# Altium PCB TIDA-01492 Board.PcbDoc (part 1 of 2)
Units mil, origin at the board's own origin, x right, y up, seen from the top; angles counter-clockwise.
Board outline 4930.03 x 2625.03 mil, 4 copper layers (Top Layer, Signal Layer 1, Signal Layer 2, Bottom Layer), stack 38.4 mil thick; 141 components, 49 nets, 383 pads, 426 vias.
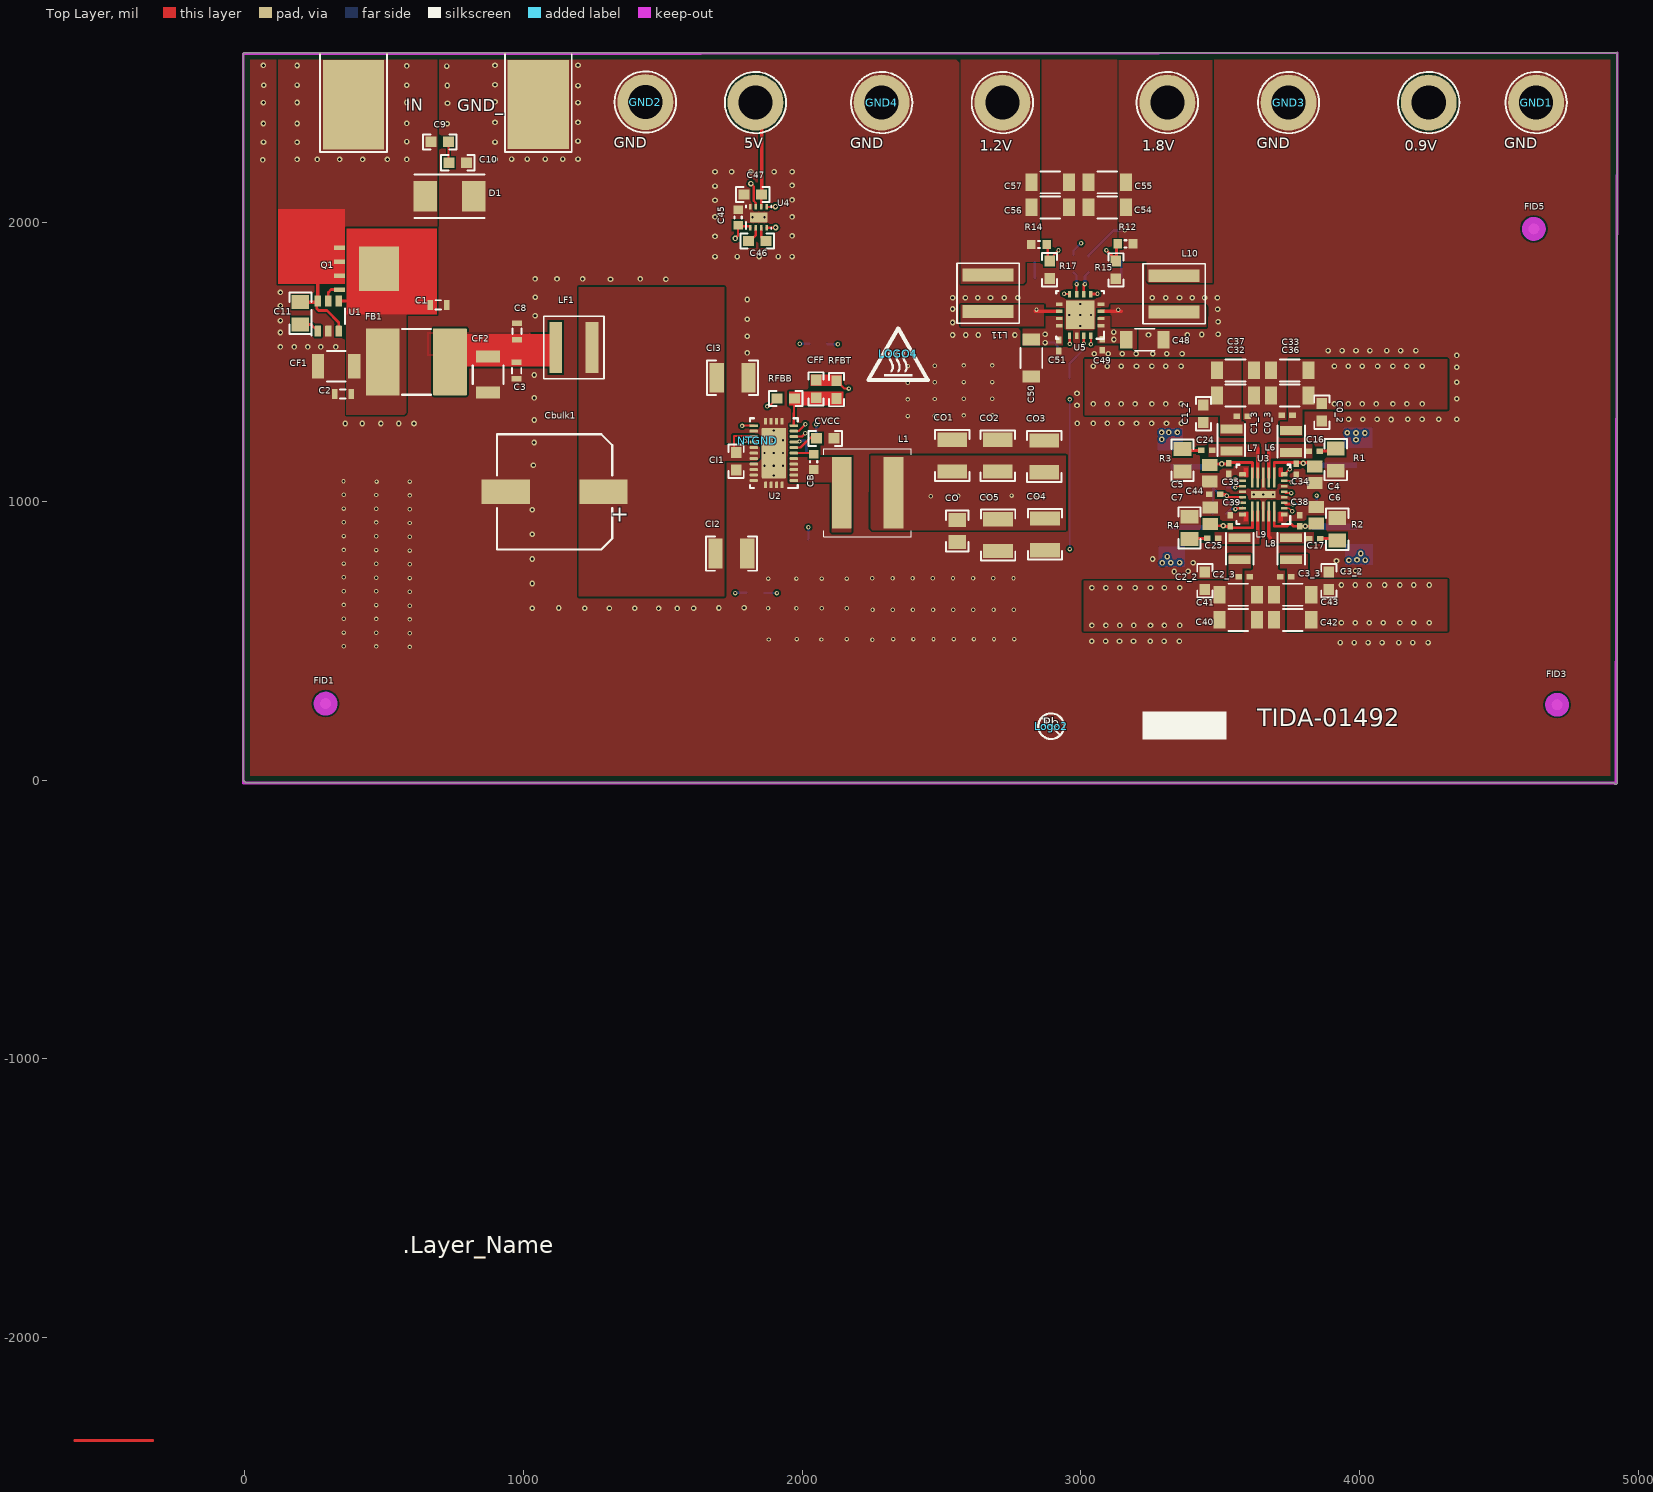
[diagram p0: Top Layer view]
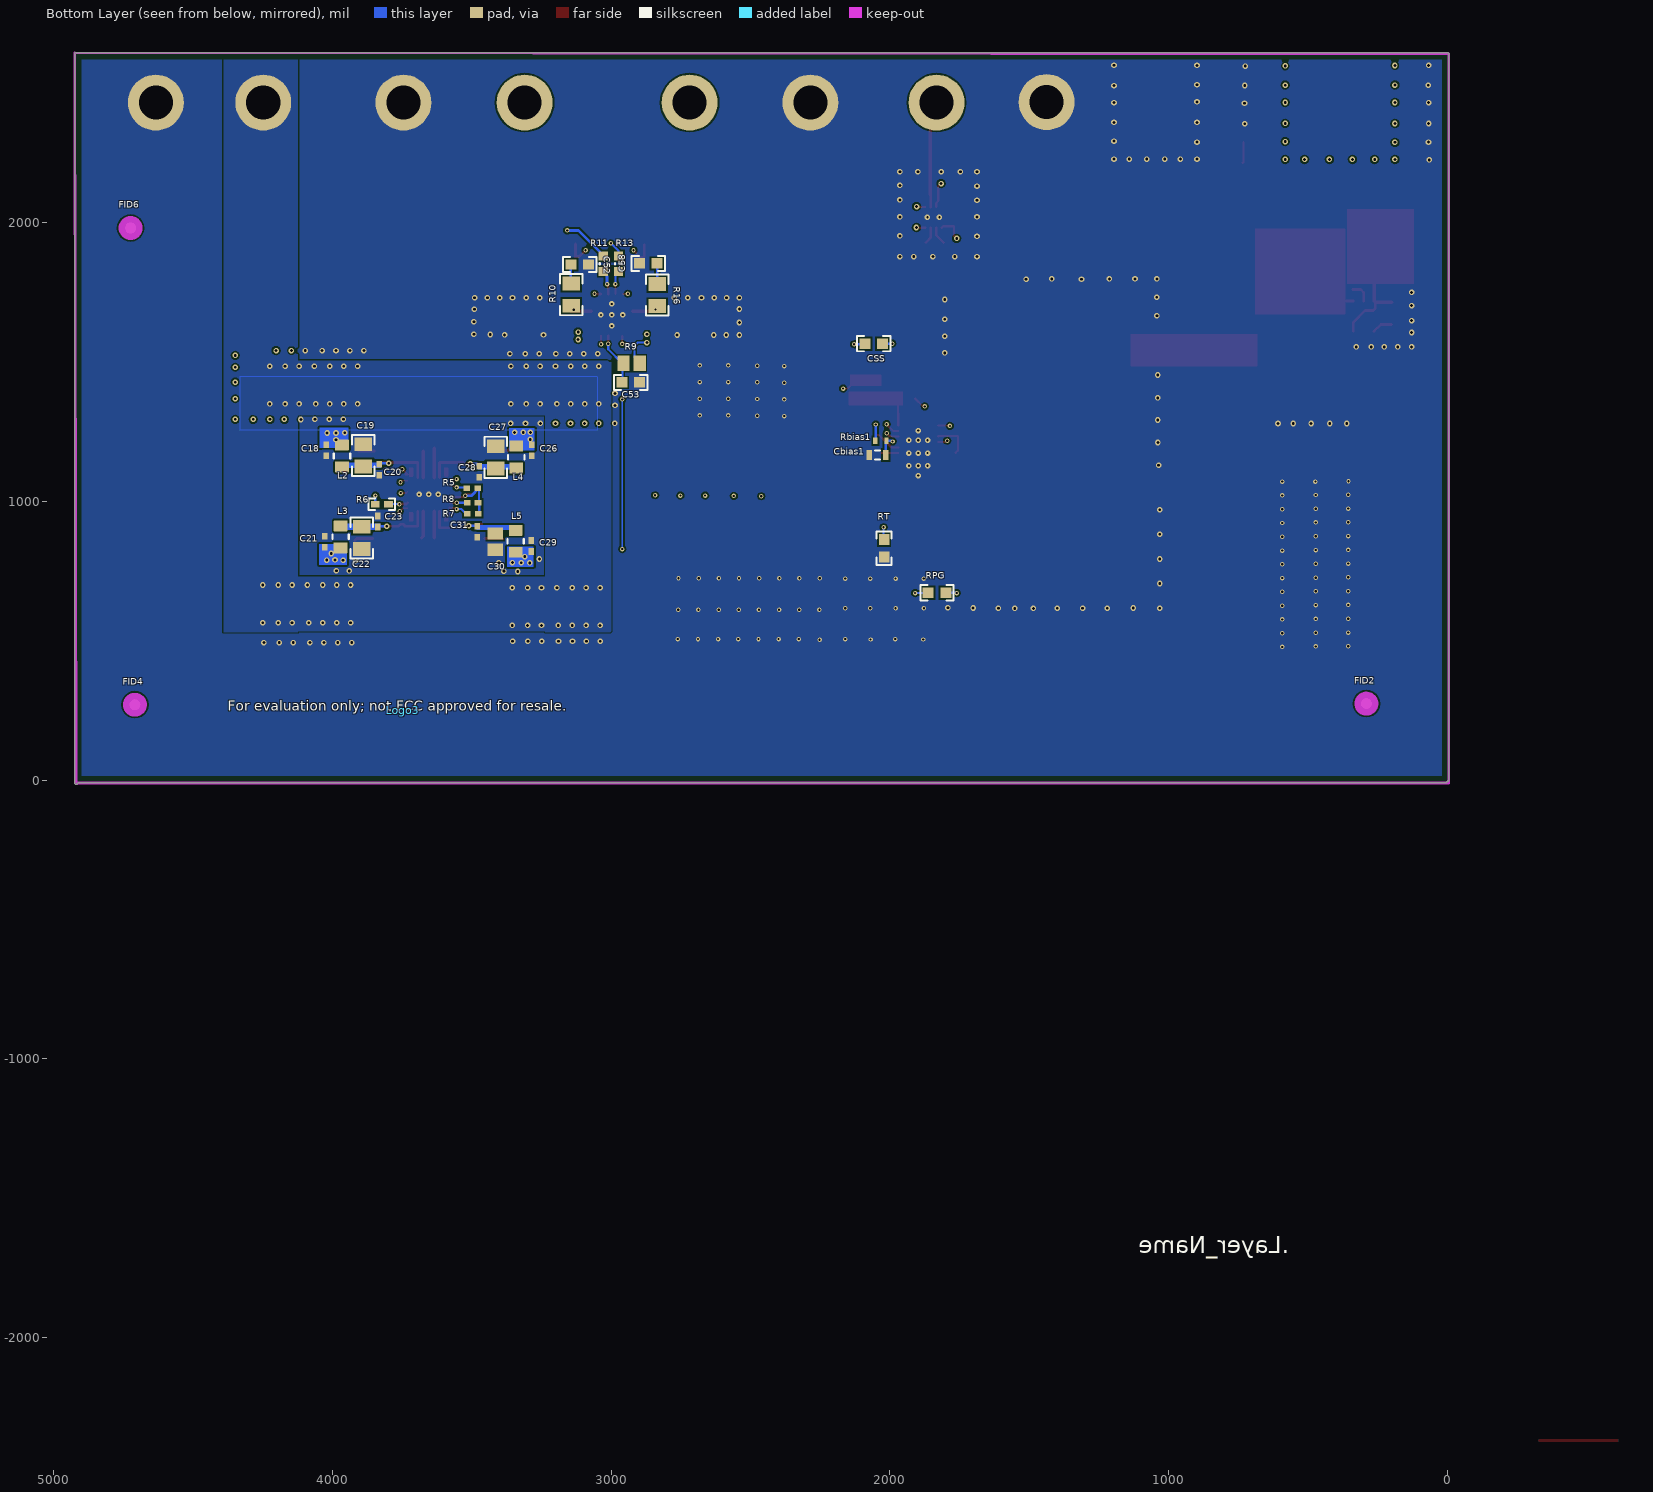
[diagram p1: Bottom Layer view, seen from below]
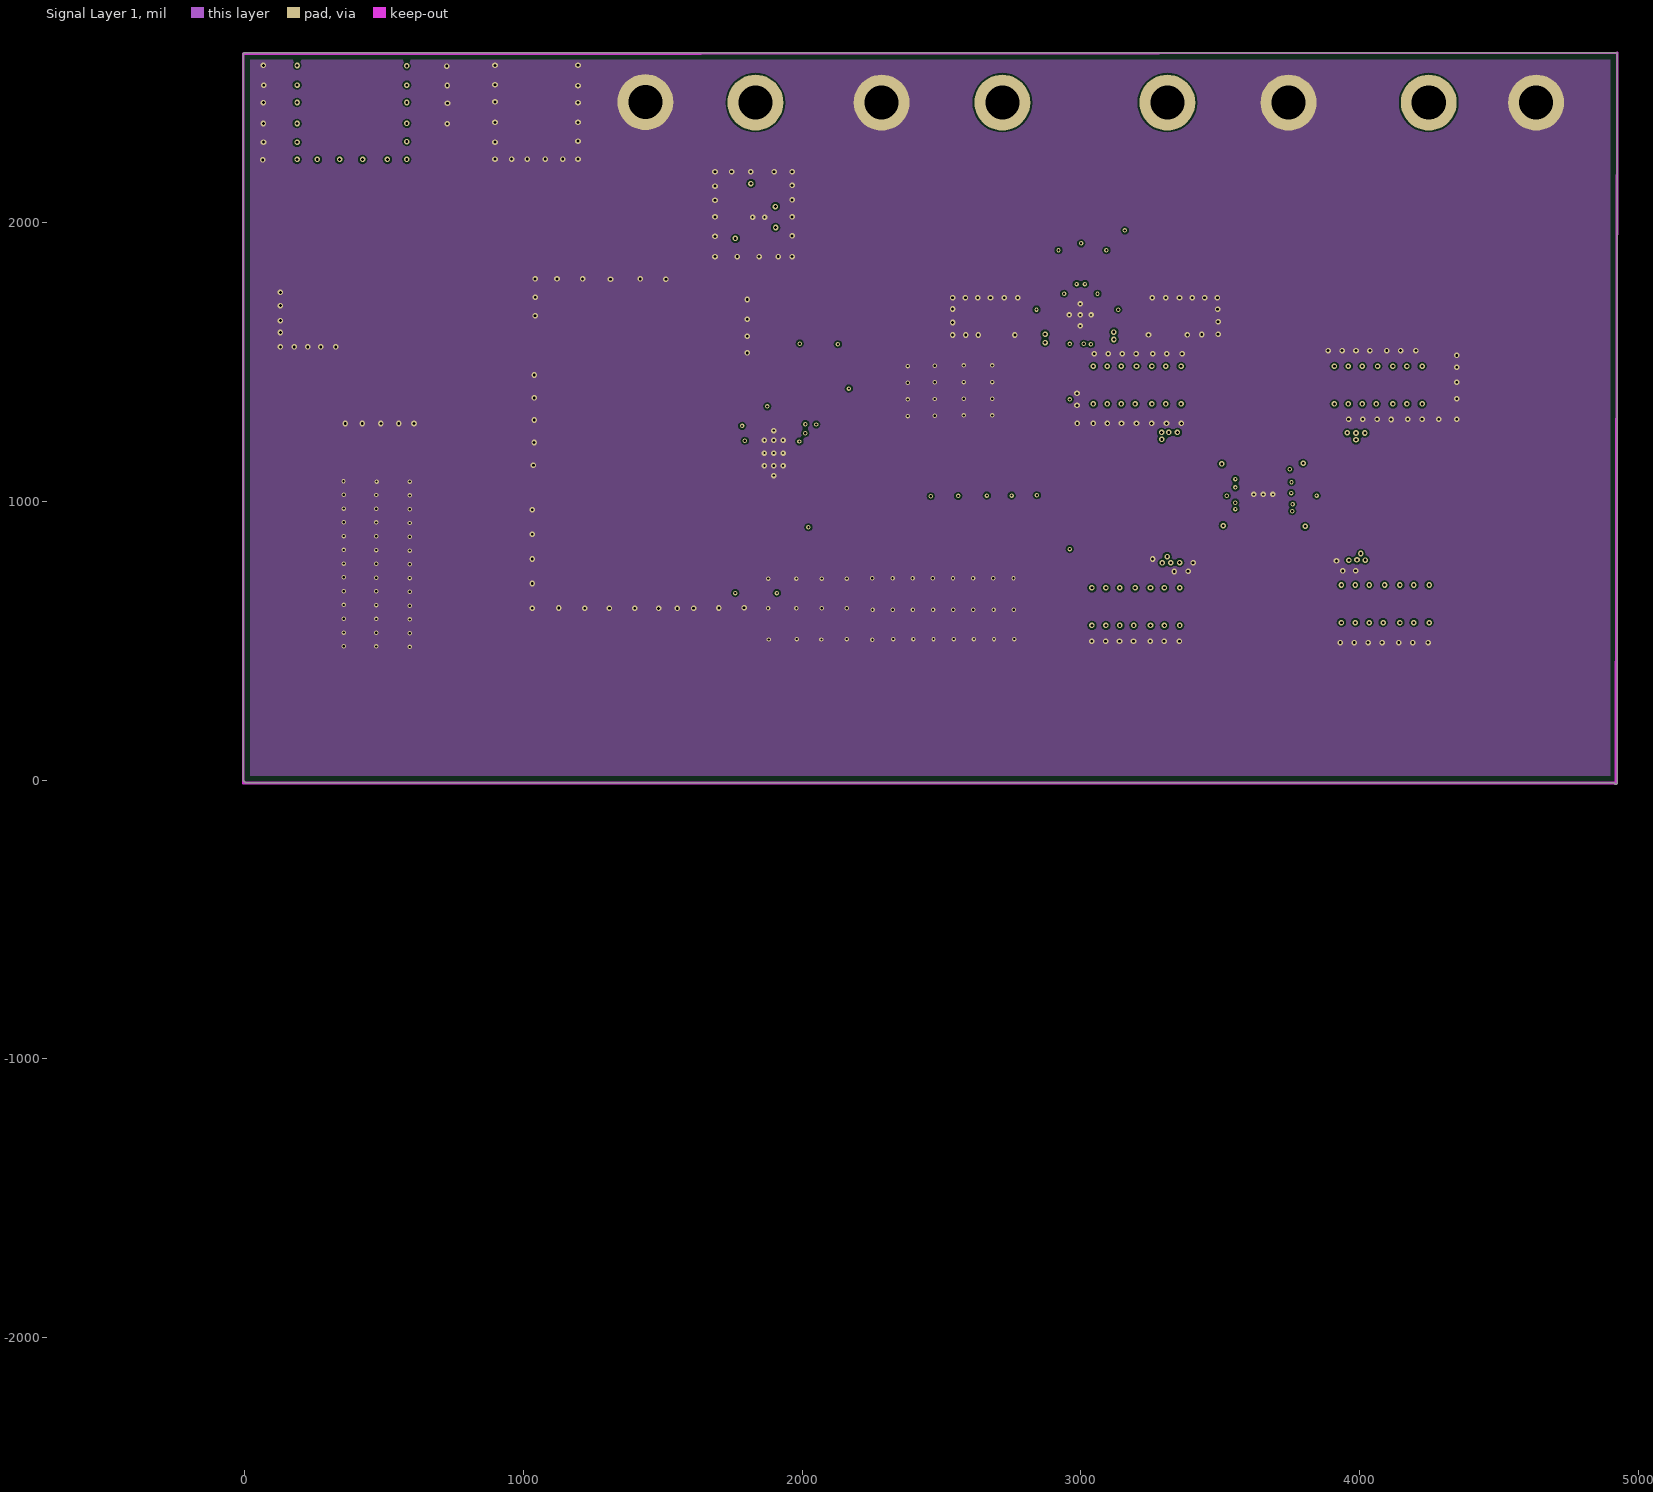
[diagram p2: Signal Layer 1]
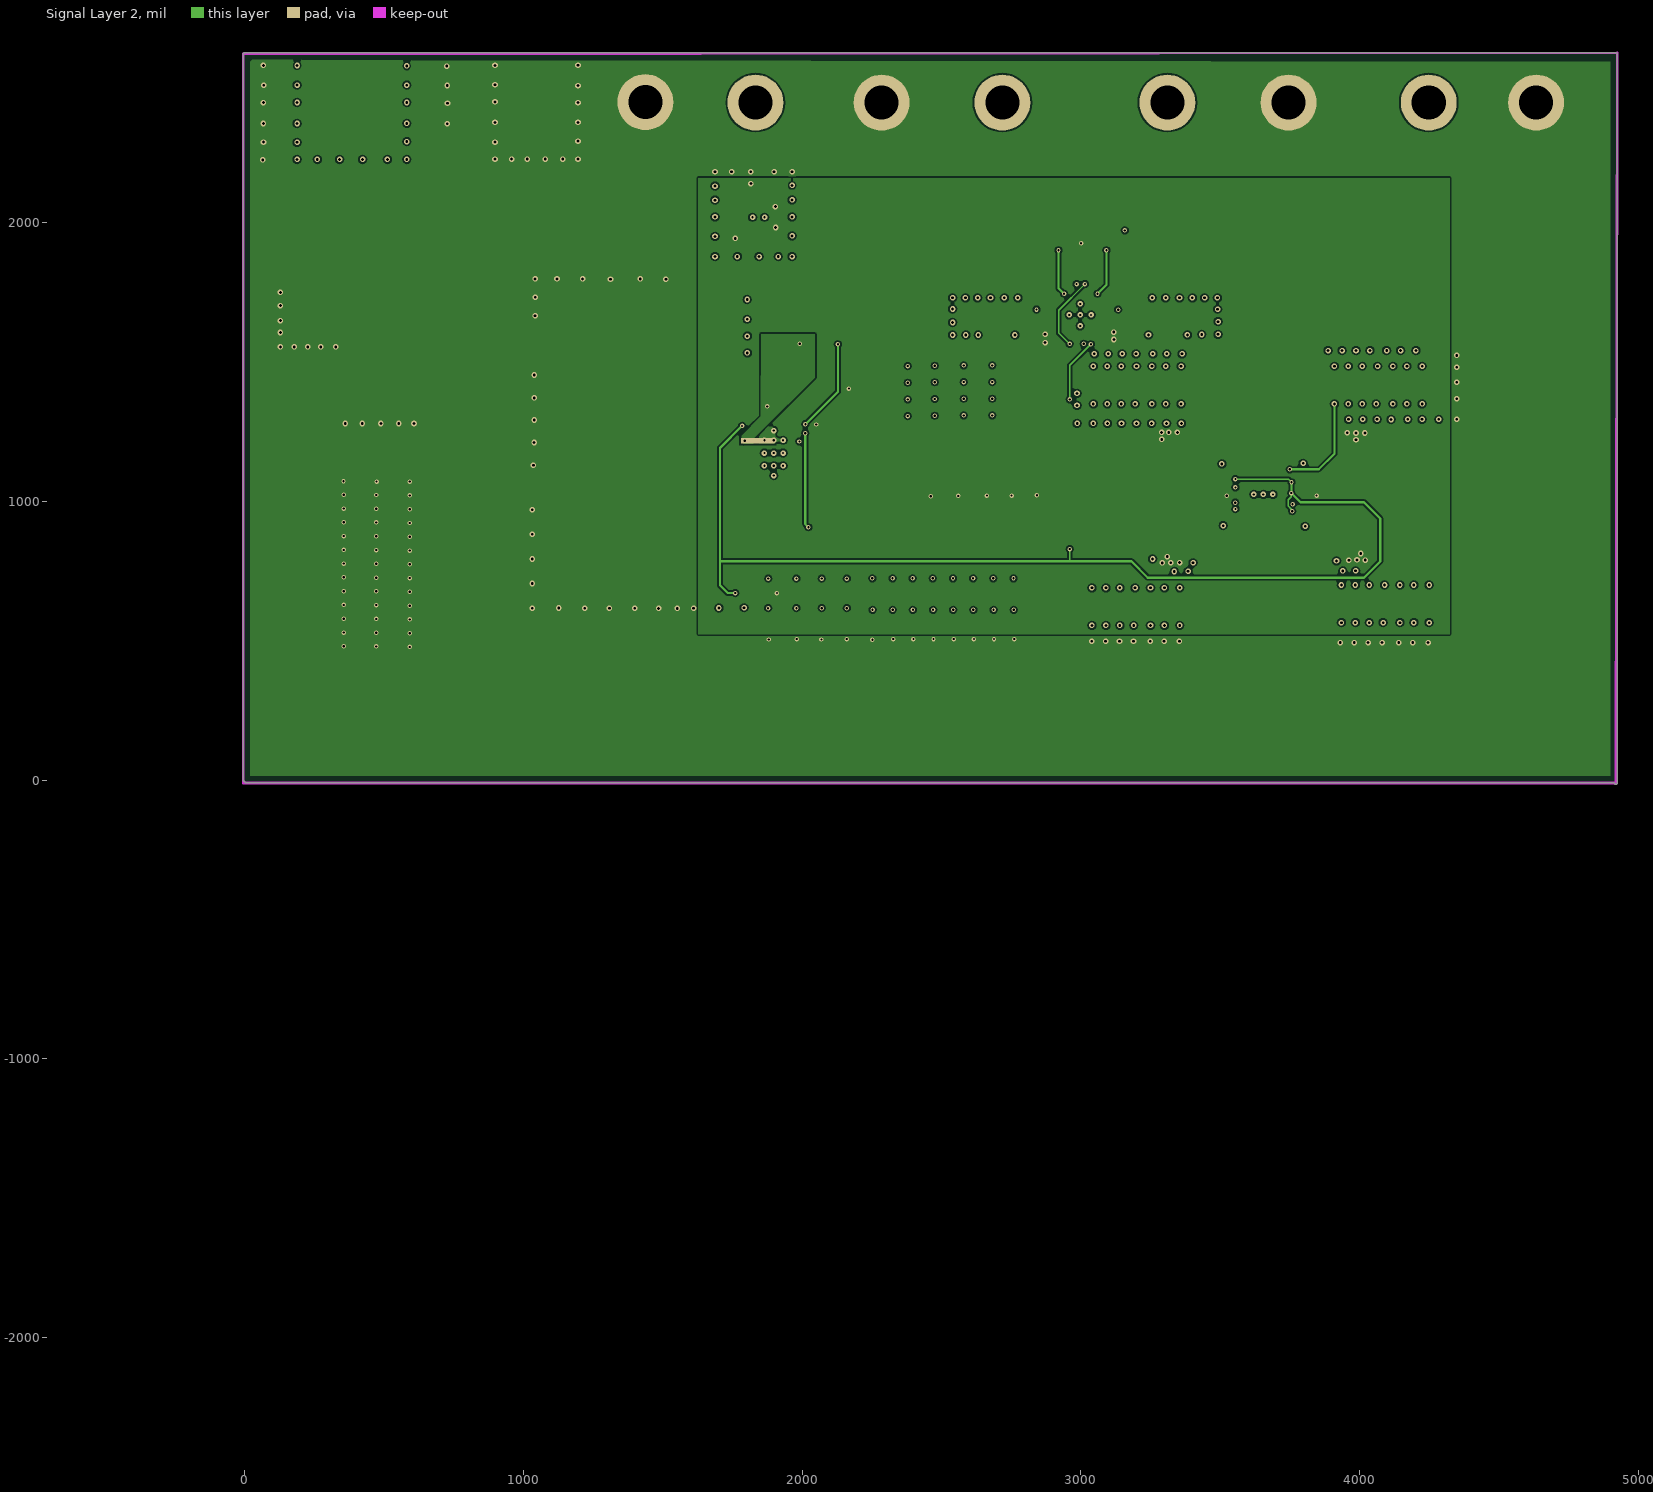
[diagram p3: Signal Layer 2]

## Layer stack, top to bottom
Top Solder: solder mask 0.4, Solder Resist, Dk 3.5
Top Layer: signal copper 2.8
Dielectric 2: core 10, FR-4, Dk 4.2
Signal Layer 1: signal copper 1.4
Dielectric 3: core 10, FR-4, Dk 4.2
Signal Layer 2: signal copper 1.4
Dielectric1: core 10, FR-4, Dk 4.2
Bottom Layer: signal copper 2.8
Bottom Solder: solder mask 0.4, Solder Resist, Dk 3.5

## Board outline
-0.01,-5.01 cw(c0,0) -5.01,0 -5.01,2605 cw(c0,2605) 0,2610.02 4920,2610.02 cw(c4920,2605) 4925.02,2605 4925.02,-10 cw(c4920,-10) 4914.98,-10.01 5,-10.01 cw(c5,-5)

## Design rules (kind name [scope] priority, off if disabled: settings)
AcuteAngle [All] p1: minimum=4.50000000000000E+0001 checktracksonly=FALSE
AssemblyTestPointUsage [All] p1: valid=2
BoardOutlineClearance BoardOutlineClearance_MountingHoles [OnCopper and InComponentClass('Mounting Holes')] p1: gap=40 ignorepadtopadclearanceinfootprint=FALSE
BoardOutlineClearance BoardOutlineClearance_Poly [OnCopper and IsPoly] p2: gap=25 ignorepadtopadclearanceinfootprint=FALSE
BoardOutlineClearance [OnCopper and Not InComponentClass('Logo') and not InComponentClass('FiducialMark') and not InRegion(1000,500,4000,800) and not InPoly] p3: gap=25 ignorepadtopadclearanceinfootprint=FALSE
Clearance Clearance_Keepouts [((IsTrack Or IsArc) And Not InPoly) And IsFree and IsKeepOut vs ((IsTrack Or IsArc) And Not InPoly) And IsFree and IsKeepOut] p1: gap=0 ignorepadtopadclearanceinfootprint=FALSE
Clearance Clearance_Poly [InPolygon] p2: gap=6 ignorepadtopadclearanceinfootprint=FALSE except(0: Arc-Hole Track-Hole SMDPad-Hole THPad-Hole Via-Hole Fill-Hole Poly-Hole Region-Hole Text-Hole)
Clearance [All] p3: gap=5 ignorepadtopadclearanceinfootprint=FALSE except(0: Arc-Hole Track-Hole SMDPad-Hole THPad-Hole Via-Hole Fill-Hole Poly-Hole Region-Hole Text-Hole)
ComponentClearance ComponentClearance_MountingHoles_FiducialMarks [InComponentClass('Mounting Holes') vs InComponentClass('FiducialMark')] p1: gap=50 collisioncheckmode=3 verticalgap=10 showdistances=TRUE
ComponentClearance ComponentClearance_Shunt [InComponentClass('Header') vs InComponentClass('Shunt')] p2: gap=0 collisioncheckmode=3 verticalgap=0 showdistances=FALSE
ComponentClearance ComponentClearance_Logo [InComponentClass('Logo')] p3: gap=50 collisioncheckmode=3 verticalgap=10 showdistances=FALSE
ComponentClearance ComponentClearance_ScrewToNut [(HasFootprint('NY PMS 440 0025 PH')) vs (HasFootprint('Keystone_1902C'))] p4: gap=5 collisioncheckmode=3 verticalgap=10 showdistances=FALSE
ComponentClearance ComponentClearance_MountingHoles [InComponentClass('Mounting Holes')] p5: gap=250 collisioncheckmode=3 verticalgap=100000 showdistances=FALSE
ComponentClearance ComponentClearance_SmallPassives [HasFootprint('0201*') or HasFootprint('0402*') or HasFootprint('0508') or HasFootprint('0603*') or HasFootprint('0612') or HasFootprint('0805*') or HasFootprint('0815*') or HasFootprint('0830*') or HasFootprint('1206*') or HasFootprint('1210*') or HasFootprint('1808*') or HasFootprint('1812*') or HasFootprint('1825*') or HasFootprint('2010*') or HasFootprint('2220*') or HasFootprint('2225*') or HasFootprint('2512*') or HasFootprint('2728*') or HasFootprint('3518*') vs HasFootprint('0201*') or HasFootprint('0402*') or HasFootprint('0508') or HasFootprint('0603*') or HasFootprint('0612') or HasFootprint('0805*') or HasFootprint('0815*') or HasFootprint('0830*') or HasFootprint('1206*') or HasFootprint('1210*') or HasFootprint('1808*') or HasFootprint('1812*') or HasFootprint('1825*') or HasFootprint('2010*') or HasFootprint('2220*') or HasFootprint('2225*') or HasFootprint('2512*') or HasFootprint('2728*') or HasFootprint('3518*')] p6: gap=14.96 collisioncheckmode=3 verticalgap=10 showdistances=FALSE
ComponentClearance ComponentClearance_THtoSMT [IsThruComponent vs IsSMTComponent] p7: gap=40 collisioncheckmode=3 verticalgap=30 showdistances=FALSE
ComponentClearance ComponentClearance_THtoTH [IsThruComponent vs IsThruComponent] p8: gap=30 collisioncheckmode=3 verticalgap=30 showdistances=FALSE
ComponentClearance [InComponent('No Component') vs InComponent('No Component')] p9: gap=10 collisioncheckmode=3 verticalgap=10 showdistances=FALSE
DiffPairsRouting [All] p1: maxlimit=100 minlimit=10 mostfreqgap=10 toplayer_minwidth=15 toplayer_maxwidth=15 toplayer_prefwidth=15 midlayer1_minwidth=15 midlayer1_maxwidth=15 midlayer1_prefwidth=15 midlayer2_minwidth=15 midlayer2_maxwidth=15 midlayer2_prefwidth=15 bottomlayer_minwidth=15 bottomlayer_maxwidth=15 bottomlayer_prefwidth=15 maxuncoupledlength=1000
FabricationTestPointUsage TestPointUsage [All] p1: valid=2 allowmultiple=FALSE
FabricationTestpoint Testpoint [All] p1: side=3 testpointundercomponent=TRUE minsize=40 maxsize=100 preferedsize=60 minholesize=0 maxholesize=40 preferedholesize=32 testpointgrid=1 allowsidetop=TRUE allowsidebottom=TRUE usegrid=TRUE gridtolerance=0.01
FanoutControl Fanout_LCC [IsLCC] p1: bgadir=Out bgaviamode=Centered fanoutstyle=Auto fanoutdirection=Alternating viagrid=1 // Fanout_LCC (Default Rule)
FanoutControl Fanout_BGA [IsBGA] p2: bgadir=Out bgaviamode=Centered fanoutstyle=Auto fanoutdirection=Alternating viagrid=1 // Fanout_BGA (Default Rule)
FanoutControl Fanout_Default [All] p4: bgadir=Out bgaviamode=Centered fanoutstyle=Auto fanoutdirection=Alternating viagrid=1 // Fanout_Default (Default Rule)
FanoutControl Fanout_Small [(CompPinCount < 5)] p5: bgadir=Out bgaviamode=Centered fanoutstyle=Auto fanoutdirection=OutThenIn viagrid=1 // Fanout_Small (Default Rule)
HoleSize [All] p1: absolutevalues=TRUE maxlimit=251 minlimit=7.87 maxpercent=80.000 minpercent=20.000
MinimumAnnularRing MinimumAnnularRing_ThermalPadVias [IsVia and InAnyComponent] p1: minimumring=5.91
MinimumAnnularRing [All] p2: minimumring=4
MinimumSolderMaskSliver MinimumSolderMaskSliver_Logo [InComponentClass('Logo') vs InComponentClass('Logo')] p1: minsoldermaskwidth=0.7
MinimumSolderMaskSliver [All] p2: minsoldermaskwidth=3.94
PlaneConnect [All] p1: planeconnectstyle=Relief reliefexpansion=10 reliefentries=4 reliefconductorwidth=10 reliefairgap=10
PolygonConnect [All] p1: connectstyle=Direct reliefconductorwidth=10 reliefentries=4 polygonreliefangle="90 Angle" airgapwidth=10
RoomDefinition TIDA-01492_EVM_Hardware [InComponentClass('TIDA-01492_EVM_Hardware')] p1 off: confinementstyle=ConfineIn formatcopy=TRUE lockcomponents=FALSE outline -702,-2374 1298,-2374 1298,-1374 -702,-1374
RoomDefinition "Memory + IO + CAN Supply" [InComponentClass('Memory + IO + CAN Supply')] p2 off: confinementstyle=ConfineIn formatcopy=TRUE lockcomponents=FALSE outline -702,-2374 1298,-2374 1298,-1374 -702,-1374
RoomDefinition "Main Supply + Smart Diode" [InComponentClass('Main Supply + Smart Diode')] p3 off: confinementstyle=ConfineIn formatcopy=TRUE lockcomponents=FALSE outline -702,-2374 1298,-2374 1298,-1374 -702,-1374
RoomDefinition "Core-Voltage Supply" [InComponentClass('Core-Voltage Supply')] p4 off: confinementstyle=ConfineIn formatcopy=TRUE lockcomponents=FALSE outline -702,-2374 1298,-2374 1298,-1374 -702,-1374
RoutingVias ThermalPadVias [IsVia and InAnyComponent] p1: holewidth=7.87 width=19.68 viastyle="Through Hole" minholewidth=7.87 minwidth=19.68 maxholewidth=12.99 maxwidth=23.62
RoutingVias [All] p2: holewidth=16 width=34 viastyle="Through Hole" minholewidth=8 minwidth=16 maxholewidth=40 maxwidth=65
SilkToBoardRegionClearance [Not ((IsComment or IsDesignator) And (Hide <> 'False')) and not InRegion(1000,500,4000,800)] p1:
SilkToSilkClearance SilkToSilkClearance_Pb-FreeLogo [(HasFootprint('Pb-Free_Overlay_Medium') OR HasFootprint('Pb-Free_Overlay_Small')) vs (HasFootprint('Pb-Free_Overlay_Medium') OR HasFootprint('Pb-Free_Overlay_Small'))] p1: silktosilkclearance=0
SilkToSilkClearance [All] p2: silktosilkclearance=4
SilkToSolderMaskClearance SilkToComponentPadClearance [(IsPad or IsFill or IsRegion) and InAnycomponent] p1: minsilkscreentomaskgap=5 clearancetoexposedcopper=TRUE
SilkToSolderMaskClearance "Silk to Solder Mask Opening" [All] p2: minsilkscreentomaskgap=4 clearancetoexposedcopper=FALSE
SolderMaskExpansion [All] p1: expansion=1.97
Width [All] p1: maxlimit=100 minlimit=6 preferedwidth=10 checkconnectedcopper=TRUE
15 further rules are at their usual default settings.

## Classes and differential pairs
component class TIDA-01492_EVM_Hardware: !PCB1 FID1 FID2 FID3 FID4 FID5 FID6 Logo2 Logo3
component class "Main Supply + Smart Diode": C1 C2 C3 C8 C9 C10 C11 CB Cbias1 Cbulk1 CF1 CF2 CFF CI1 CI2 CI3 CO CO1 CO2 CO3 CO4 CO5 CSS CVCC D1 FB1 GND_ IN L1 LF1 LOGO4 NTGND Q1 R_FB1 Rbias1 RFBB RFBT RPG RT U1 U2
component class "Core-Voltage Supply": 0.9V C0_2 C0_3 C1_1 C1_2 C1_3 C2_2 C2_3 C3_2 C3_3 C4 C5 C6 C7 C16 C17 C18 C19 C20 C21 C22 C23 C24 C25 C26 C27 C28 C29 C30 C31 C32 C33 C34 C35 C36 C37 C38 C39 C40 C41 C42 C43 C44 GND1 L2 L3 L4 L5 L6 L7 L8 L9 R1 R2 R3 R4 R5 R6 R7 R8 U3
component class "Memory + IO + CAN Supply": 1.2V 1.8V 5V C45 C46 C47 C48 C49 C50 C51 C52 C53 C54 C55 C56 C57 C58 C59 C60 GND2 GND3 GND4 L10 L11 R9 R10 R11 R12 R13 R14 R15 R16 R17 U4 U5

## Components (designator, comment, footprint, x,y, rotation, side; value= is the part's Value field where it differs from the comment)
0.9V "0.9V" Keystone1503-2 4248.5,2431 r0 top value=Double
1.2V "1.2V" Keystone1503-2 2718.5,2431 r0 top value=Double
1.8V "2010-10-20" Keystone1503-2 3310.5,2431 r0 top value=Double
5V "5V" Keystone1503-2 1832.5,2431 r0 top value=Double
C0_2 "GRM188R71C104KA01D" 0603 3865,1320 r90 top value=0.1uF
C0_3 "GRM155R71H332KA01D" 0402L 3740,1310 r180 top value=3300pF
C1 "GCM188R71C104KA37J" 0603S 695,1705 r0 top value=0.1uF
C1_2 "GRM188R71C104KA01D" 0603 3440,1315 r90 top value=0.1uF
C1_3 "GRM155R71H332KA01D" 0402L 3580,1305 r0 top value=3300pF
C2 "GCM188R71C104KA37J" 0603S 352.5,1385.5 r180 top value=0.1uF
C2_2 "GRM188R71C104KA01D" 0603 3445,715 r270 top value=0.1uF
C2_3 "GRM155R71H332KA01D" 0402L 3586,729.5 r0 top value=3300pF
C3 "GCM188R71C104KA37J" 0603S 975.5,1469.5 r270 top value=0.1uF
C3_2 "GRM188R71C104KA01D" 0603 3890,715 r270 top value=0.1uF
C3_3 "GRM155R71H332KA01D" 0402L 3735,730 r180 top value=3300pF
C4 "GCM21BR71A106KE22L" 0805L 3840,1095 r270 top value=10uF
C5 "GCM21BR71A106KE22L" 0805L 3463,1101 r90 top value=10uF
C6 "GCM21BR71A106KE22L" 0805L 3845,950 r90 top value=10uF
C7 "GCM21BR71A106KE22L" 0805L 3465,949 r270 top value=10uF
C8 "GCM188R71C104KA37J" 0603S 977,1610 r90 top value=0.1uF
C9 "C0603C472J1GAC7867" 0603 700,2290 r0 top value=4700pF
C10 "C0603C472J1GAC7867" 0603 765,2215 r180 top value=4700pF
C11 "C2012X5R1H225K125AB" 0805_HV 200,1675 r270 top value=2.2uF
C16 "GRM155R71H391KA01D" 0402L 3837,1180.5 r0 top value=390pF
C17 "GRM155R71H391KA01D" 0402L 3840,866.5 r0 top value=390pF
C18 "GRM155R71H682KA88D" 0402L 4022,1183 r270 bottom value=6800pF
C19 "GRM21BR60J106KE19L" 0805_HV 3889.58,1165 r90 bottom value=10uF
C20 "GRM155R71C104JA88D" 0402L 3833,1114 r90 bottom value=0.1uF
C21 "GRM155R71H682KA88D" 0402L 4027,855.5 r90 bottom value=6800pF
C22 "GRM21BR60J106KE19L" 0805_HV 3895,869 r270 bottom value=10uF
C23 "GRM155R71C104JA88D" 0402L 3838,928 r270 bottom value=0.1uF
C24 "GRM155R71H391KA01D" 0402L 3452.5,1183 r180 top value=390pF
C25 "GRM155R71H391KA01D" 0402L 3474,867 r180 top value=390pF
C26 "GRM155R71H682KA88D" 0402L 3284.5,1183 r270 bottom value=6800pF
C27 "GRM21BR60J106KE19L" 0805_HV 3414,1158 r90 bottom value=10uF
C28 "GRM155R71C104JA88D" 0402L 3474,1107 r90 bottom value=0.1uF
C29 "GRM155R71H682KA88D" 0402L 3287,840 r90 bottom value=6800pF
C30 "GRM21BR60J106KE19L" 0805L 3416,856 r270 bottom value=10uF
C31 "GRM155R71C104JA88D" 0402L 3480.5,891.5 r90 bottom value=0.1uF
C32 "GCM31CR71A106KA64L" 1206_180 3555,1380 r0 top value=10uF
C33 "GCM31CR71A106KA64L" 1206_180 3750,1470 r180 top value=10uF
C34 "GRM155R71C104JA88D" 0402L 3773,1115 r90 top value=0.1uF
C35 "GRM155R71C104JA88D" 0402L 3531,1118 r270 top value=0.1uF
C36 "GCM31CR71A106KA64L" 1206_180 3750,1380 r180 top value=10uF
C37 "GCM31CR71A106KA64L" 1206_180 3555,1470 r0 top value=10uF
C38 "GRM155R71C104JA88D" 0402L 3785,930 r270 top value=0.1uF
C39 "GRM155R71C104JA88D" 0402L 3536,930 r90 top value=0.1uF
C40 "GCM31CR71A106KA64L" 1206_180 3565,575 r0 top value=10uF
C41 "GCM31CR71A106KA64L" 1206_180 3565,665 r0 top value=10uF
C42 "GCM31CR71A106KA64L" 1206_180 3760,575 r180 top value=10uF
C43 "GCM31CR71A106KA64L" 1206_180 3760,665 r180 top value=10uF
C44 "GRM155R71C104JA88D" 0402L 3480,1025 r180 top value=0.1uF
C45 "GRM188R61A225KE34D" 0603L 1770.32,2018.75 r90 top value=2.2uF
C46 "C0603C105K8PACTU" 0603 1838.84,1934.35 r180 top value=1uF
C47 "GRM188R61A225KE34D" 0603 1823.34,2101.35 r180 top value=2.2uF
C48 "GCM31CR71A106KA64L" 1206_180 3230,1580 r0 top value=10uF
C49 "GRM155R71C104JA88D" 0402L 3076.5,1561.5 r90 top value=0.1uF
C50 "GCM31CR71A106KA64L" 1206_180 2822.5,1514.5 r270 top value=10uF
C51 "GRM155R71C104JA88D" 0402L 2921.5,1559.5 r90 top value=0.1uF
C52 "C0603C222K5RACTU" 0603 3113,1850 r180 bottom value=2200pF
C53 "GRM188R71A474KA61D" 0603 2930,1427 r180 bottom value=0.47uF
C54 "GCM31CR71A226KE02" 1206_180 3095,2055 r180 top value=22uF
C55 "GCM31CR71A226KE02" 1206_180 3095,2145 r180 top value=22uF
C56 "GCM31CR71A226KE02" 1206_180 2890,2055 r0 top value=22uF
C57 "GCM31CR71A226KE02" 1206_180 2890,2145 r0 top value=22uF
C58 "C0603C222K5RACTU" 0603 2867,1854 r0 bottom value=2200pF
CB "GRM188R61E474KA12D" 0603L 2041.5,1142 r270 top value=0.47uF
Cbias1 "GCM188R71C104KA37J" 0603S 2044.5,1166.5 r0 bottom value=0.1uF
Cbulk1 "HHXB500ARA101MJA0G" HXB_JA0 1112,1034.5 r180 top value=100uF
CF1 "CGA6P3X7R1H475M250AB" 1210_280 328,1485 r180 top value=4.7uF
CF2 "CGA6P3X7R1H475M250AB" 1210_280 873,1455 r270 top value=4.7uF
CFF "06035A4R7CAT2A" 0603 2050,1403.5 r270 top value=4.7pF
CI1 "GRM21BR71H474KA88L" 0603 1763.5,1143.5 r90 top value=0.47uF
CI2 "GRM32ER71H106KA12L" 1210_270 1746.5,813 r180 top value=10uF
CI3 "GRM32ER71H106KA12L" 1210_270 1750.5,1444 r180 top value=10uF
CO "GRM21BR71H474KA88L" 0805_HV 2556.5,894 r90 top value=0.47uF
CO1 "GRM32ER71C226KE18L" 1210_270 2538.5,1164.5 r90 top value=22uF
CO2 "GRM32ER71C226KE18L" 1210_270 2702.5,1164 r90 top value=22uF
CO3 "GRM32ER71C226KE18L" 1210_270 2869,1161.5 r90 top value=22uF
CO4 "GRM32ER71C226KE18L" 1210_270 2871.5,882 r270 top value=22uF
CO5 "GRM32ER71C226KE18L" 1210_270 2703,879 r270 top value=22uF
CSS "06031C103MAT2A" 0603 2058,1566 r180 bottom value=0.01uF
CVCC "GRM188C81A225KE34D" 0603 2083.5,1226 r0 top value=2.2uF
D1 "SMBJ28CA-13-F" SMB-Bi 735,2095 r0 top value=28V
FB1 "HR2220V801R-10" 2220_390 616,1500.5 r0 top value="800 ohm"
FID1 "Fiducial" Fiducial10-20 290.15,274.31 r0 top
FID2 "Fiducial" Fiducial10-20 290.15,274.31 r180 bottom
FID3 "Fiducial" Fiducial10-20 4709,270.5 r0 top
FID4 "Fiducial" Fiducial10-20 4709,270.5 r180 bottom
FID5 "Fiducial" Fiducial10-20 4625.5,1978 r0 top
FID6 "Fiducial" Fiducial10-20 4724.5,1981 r180 bottom
GND1 "GND" Keystone1503-2 4634,2431 r0 top value=Double
GND2 "GND" Keystone1503-2 1437.5,2433 r0 top value=Double
GND3 "GND" Keystone1503-2 3745.5,2431 r0 top value=Double
GND4 "GND" Keystone1503-2 2285.5,2431 r0 top value=Double
GND_ "GROUND" 6092 1053.5,2609 r270 top
IN "INPUT" 6091 390,2608 r270 top
L1 "XAL7030-222MEB" XAL7030 2235,1031 r0 top value=2.2uH
L2 "BLM21PG300SH1D" 0805_HV1 3966,1163 r270 bottom value="30 ohm"
L3 "BLM21PG300SH1D" 0805_HV1 3971,873 r90 bottom value="30 ohm"
L4 "BLM21PG300SH1D" 0805_HV1 3341,1159 r270 bottom value="30 ohm"
L5 "BLM21PG300SH1D" 0805_HV1 3343,857 r90 bottom value="30 ohm"
L6 "DFE252012F-R47M=P2" DFE252012C 3755,1215 r90 top value=470nH
L7 "DFE252012F-R47M=P2" DFE252012C 3540,1220 r90 top value=470nH
L8 "DFE252012F-R47M=P2" DFE252012C 3755,830 r270 top value=470nH
L9 "DFE252012F-R47M=P2" DFE252012C 3570,830 r270 top value=470nH
L10 "XAL5030-122MEB" XAL5030 3335,1745 r90 top value=1.2uH
L11 "XAL5030-122MEB" XAL5030 2667.5,1747 r90 top value=1.2uH
LF1 "XAL5030-222MEB" XAL5030 1181,1552.5 r0 top value=2.2uH
Logo2 "Pb-Free Symbol" Pb-Free_Overlay_Small 2893.5,193.5 r0 top
Logo3 "FCC disclaimer" FCC_disclaimer 3748.5,250.5 r180 bottom
LOGO4 "CAUTION HOT SURFACE" IEC_HotSurface_Small 2344.5,1529 r0 top
NTGND "Net-Tie" Net-Tie_20milWide_60milLong 1841,1218 r180 top net-tie
Q1 "SQJ422EP-T1-GE3" PowerPAK_SO-8L 450,1835 r0 top value=40V
R1 "CRCW08053R90JNEA" 0805_HV 3915,1150 r90 top value=3.9
R2 "CRCW08053R90JNEA" 0805_HV 3920,900 r270 top value=3.9
R3 "CRCW08053R90JNEA" 0805_HV 3365,1147.5 r90 top value=3.9
R4 "CRCW08053R90JNEA" 0805_HV 3390,905 r270 top value=3.9
R5 "CRCW0402100KFKED" 0402L 3498,1048 r0 bottom value=100k
R6 "CRCW0402100KFKED" 0402 3823,990.5 r180 bottom value=100k
R7 "CRCW0402100KFKED" 0402L 3497,955.5 r0 bottom value=100k
R8 "CRCW0402100KFKED" 0402L 3497.5,995.5 r0 bottom value=100k
R9 "RC0805FR-074R99L" 0805L 2927,1496 r0 bottom value=4.99
R10 "CRCW08054R70JNEA" 0805_HV 3143.5,1742 r90 bottom value=4.7
R11 "CRCW060349K9FKEA" 0603L 3028,1853 r270 bottom value=49.9k
R12 "CRCW060312K4FKEA" 0603L 3160,1924 r0 top value=12.4k
R13 "CRCW060349K9FKEA" 0603L 2974,1853 r270 bottom value=49.9k
R14 "CRCW06034K99FKEA" 0603L 2850,1922 r180 top value=4.99k
R15 "CRCW060310K0JNEA" 0603 3126,1830.5 r90 top value=10k
R16 "CRCW08054R70JNEA" 0805_HV 2835,1740.5 r270 bottom value=4.7
R17 "CRCW060310K0JNEA" 0603 2888,1831.5 r90 top value=10k
Rbias1 "CRCW04023R00JNED" 0402S 2032.5,1218 r0 bottom value=3.0
RFBB "CRCW0603432KFKEA" 0603 1941.69,1369.2 r0 top value=432k
RFBT "CRCW06031M00FKEA" 0603 2123.5,1401.5 r90 top value=1.00Meg
RPG "CRCW0603100KFKEA" 0603 1831,672.5 r0 bottom value=100k
RT "CRCW060317K4FKEA" 0603 2021,832 r270 bottom value=17.4k
U1 "LM74700QDBVTQ1" DDC0006A_N 230,1835 r90 top
U2 "LM73605QRNPRQ1" RNP0030A 1898.5,1173.5 r180 top
U3 "LP87561IRNFRQ1" RNF0026C 3655,1025 r180 top
U4 "LM2775DSGR" DSG0008A 1843.84,2019.35 r90 top
U5 "LM26420Q1XSQ/NOPB" RUM0016A 2997.75,1669.21 r180 top

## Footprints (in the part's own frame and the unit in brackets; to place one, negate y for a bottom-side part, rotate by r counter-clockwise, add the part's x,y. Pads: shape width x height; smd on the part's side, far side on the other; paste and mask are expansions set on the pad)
0402 [mm] "0402 from SM-752 data"
  rect 0.8x0.6 smd: 1(-0.6,0) 2(0.6,0)
  silkscreen extent -1.22,-0.52 1.22,0.52, body extent -0.55,-0.3 0.55,0.3, height 0.6
0402L [mm] "0402 from SM-752 data"
  rect 0.6x0.5 smd: 1(-0.5,0) 2(0.5,0)
  body extent -0.55,-0.3 0.55,0.3, height 0.6
0402S [mil] "Based on C0402S footprint from PADS legacy"
  rect 15x24 smd: 1(-20,0) 2(20,0)
  body extent -22,-12 22,12, height 24
0603 [mm] "0603 from SM-752 data"
  rect 1x0.95 smd: 1(-0.8,0) 2(0.8,0)
  silkscreen extent -1.52,-0.69 1.52,0.69, body extent -0.87,-0.47 0.87,0.47, height 1
0603L [mm] "0603 from SM-752 data"
  rect 0.8x0.85 smd: 1(-0.7,0) 2(0.7,0)
  silkscreen extent -0.07,-0.33 0.07,0.33, body extent -0.87,-0.47 0.87,0.47, height 1
0603S [mil]
  rect 20x35 smd: 1(-30,0) 2(30,0)
  silkscreen extent -10,-17 10,17, body extent -34,-19 34,19, height 39
0805_HV [mil] "0805 with 30mil clearance between pads"
  rect 50x63 smd: 1(-40,0) 2(40,0)
  silkscreen extent -74,-40 74,40, body extent -43,-29 43,29, height 57
0805_HV1 [mm] "Custom footprint based on analyzing multiple manufacturer recommendations"
  rrect10% 1x1.25 smd: 1(-1,0) 2(1,0)
  silkscreen extent -0.2,-0.75 0.2,0.75, body extent -1.1,-0.72 1.1,0.73, height 1.45
0805L [mm] "0805 from SM-752 data"
  rect 1.1x1.4 smd: 1(-0.75,0) 2(0.75,0)
  body extent -1.1,-0.72 1.1,0.72, height 1.45
1206_180 [mm] "1206_180"
  rect 1.1x1.6 smd: 1(-1.7,0) 2(1.7,0)
  silkscreen extent -0.9,-1 0.9,1, body extent -1.75,-0.95 1.75,0.95, height 1.8
1210_270 [mm] "1210"
  rect 1.3x2.7 smd: 1(-1.45,0) 2(1.45,0)
  silkscreen extent -2.32,-1.57 2.32,1.57, body extent -1.7,-1.35 1.7,1.35, height 2.7
1210_280 [mm] "SMD, 2-Leads, Body 3.6x2.8mm, Height 2.8mm"
  rect 1.1x2.2 smd: 1(-1.65,0) 2(1.65,0)
  silkscreen extent -0.84,-1.4 0.84,1.4, body extent -1.8,-1.4 1.8,1.4, height 2.8
2220_390 [mm] "Laird recommended land pattern"
  rrect3% 3.07x6.1 smd: 1(-3.06,0) 2(3.06,0)
  silkscreen extent -1.3,-3 1.3,3, body extent -2.8,-2.54 2.79,2.54, height 3.9
6091 [mil] "Keystone Insulated End Launch Banana Jack"
  rect 320x220 smd: 1(185,0)
  silkscreen extent 5,-120 355,120, body extent -666,-216 271,216, height 227
6092 [mil] "Keystone Insulated End Launch Banana Jack"
  rect 320x220 smd: 1(185,0)
  silkscreen extent 5,-120 355,120, body extent -666,-216 271,216, height 227
DDC0006A_N [mm]
  rrect17% 1x0.6 smd: 1(-5.693,-0.828) 2(-5.693,-1.778) 3(-5.693,-2.728) 4(-2.943,-2.728) 5(-2.943,-1.778) 6(-2.943,-0.828)
  silkscreen extent -6.07,-3.3 -3.62,-0.25, body extent -5.75,-3.26 -2.88,-0.29, height 0.92
DFE252012C [mm] "Toko"
  rect 0.8x2 smd: 1(-1,0) 2(1,0)
  silkscreen extent -1.45,-1.25 1.45,1.25, body extent -1.35,-1.1 1.35,1.1, height 1.2
DSG0008A [mm] "SON, 8-Leads, Body 2x2mm, Pitch 0.5mm, Thermal Pad 1.6x0.9mm, TI Recommended"
  rrect40% 0.5x0.25 smd: 1(-0.95,0.75) 2(-0.95,0.25) 3(-0.95,-0.25) 4(-0.95,-0.75) 5(0.95,-0.75) 6(0.95,-0.25) 7(0.95,0.25) 8(0.95,0.75)
  rrect14% 0.9x0.7 on Top Paste: 9(0,0.45) 9(0,-0.45)
  rrect11% 0.9x1.6 smd paste-0.45: 9(0,0)
  silkscreen extent -1.07,-1.15 1.07,1.15, body extent -1,-1 1,1, height 0.77
FCC_disclaimer [mil]
Fiducial10-20 [mm]
  round 1 smd mask+0.5: 1(0,0)
  Top Layer keep-out circle w1.178: c0,0 r0.5
HXB_JA0 [mm] "SMD, 2-Leads, Dia 10mm"
  rect 4.4x2.2 smd: 1(-4.45,0) 2(4.45,0)
  silkscreen extent -5.25,-5.25 5.25,5.25, body extent -5.25,-5.25 5.25,5.25, height 10.31
IEC_HotSurface_Small [mil]
  silkscreen extent -107,-93 107,92
Keystone1503-2 [mm] "Double Turret"
  round 5.1 hole 3.1: 1(0,0)
  silkscreen extent -2.79,-2.79 2.79,2.79, body extent -2.4,-2.4 2.38,2.4, height 9.22
Net-Tie_20milWide_60milLong [mil] "20mil net tie, no solder mask opening, no solder paste"
  rect 60x20 on Mid2 paste-10 mask-10: 1(-30,0) 2(30,0)
Pb-Free_Overlay_Small [mil]
  silkscreen extent -46,-46 46,46
PowerPAK_SO-8L [mm] "based on Vishay recommended land pattern Document 63818 Feb 7, 2012"
  rect 1x0.41 smd: 1(-2.805,1.905) 2(-2.805,0.635) 3(-2.805,-0.635) 4(-2.805,-1.905)
  rect 3.63x4.061 smd: 5(0.805,0)
  Top Layer region: -0.298,-2.64 0.298,-2.64 0.298,-2.03 -0.298,-2.03
  Top Layer region: -0.297,2.03 0.298,2.03 0.298,2.64 -0.297,2.64
  Top Layer region: 2.615,-2.5 3.125,-2.5 3.125,2.5 2.615,2.5
  body extent -3.07,-2.57 3.08,2.57, height 1.21
RNF0026C [mm] "QFN, 26-Leads, Body 4x4.5mm, Pitch 0.5mm"
  rrect25% 0.6x0.4 smd paste-0.3: 1(-1.9,1.825) 8(-1.9,-1.825) 14(1.9,-1.825) 21(1.9,1.825)
  rrect40% 0.6x0.25 smd paste+0: 2(-1.9,1.25) 3(-1.9,0.75) 4(-1.9,0.25) 5(-1.9,-0.25) 6(-1.9,-0.75) 7(-1.9,-1.25) 15(1.9,-1.25) 16(1.9,-0.75) 17(1.9,-0.25) 18(1.9,0.25) 19(1.9,0.75) 20(1.9,1.25)
  rrect40% 0.25x1.82 smd paste-1: 9(-1,-1.54) 10(-0.5,-1.54) 11(0,-1.54) 12(0.5,-1.54) 13(1,-1.54) 22(1,1.54) 23(0.5,1.54) 24(0,1.54) 25(-0.5,1.54) 26(-1,1.54)
  rrect15% 2.24x0.66 smd paste-1: 27(0,0)
  rrect33% 0.6x0.3 on Top Paste: ""(-1.9,1.775) ""(-1.9,-1.775) ""(1.9,1.775) ""(1.9,-1.775)
  rrect33% 0.3x0.825 on Top Paste: ""(-1.575,2.037) ""(-1.575,-2.037) ""(1.575,2.037) ""(1.575,-2.037)
  rrect40% 0.25x0.81 on Top Paste: ""(-1,1.035) ""(-1,2.045) ""(-1,-2.045) ""(-1,-1.035) ""(-0.5,2.045) ""(-0.5,1.035) ""(-0.5,-1.035) ""(-0.5,-2.045) ""(0,2.045) ""(0,1.035) ""(0,-1.035) ""(0,-2.045) ""(0.5,2.045) ""(0.5,1.035) ""(0.5,-1.035) ""(0.5,-2.045) ""(1,1.035) ""(1,2.045) ""(1,-2.045) ""(1,-1.035)
  rrect15% 0.98x0.66 on Top Paste: ""(-0.59,0) ""(0.59,0)
  Top Layer region: -2.45,2.975 -2.425,2.975 -2.4,3
  Top Layer region: -1.775,-2.4 -1.775,-1.675 -1.771,-1.656 -1.76,-1.64 -1.744,-1.629 -1.725,-1.625 -1.725,-1.625 -1.475,-1.625 -1.456,-1.629 -1.44,-1.64 -1.429,-1.656 -1.425,-1.675 -1.425,-1.675 -1.425,-2.4 -1.429,-2.419 -1.44,-2.435 -1.456,-2.446 -1.475,-2.45 -1.475,-2.45 -1.725,-2.45 -1.744,-2.446 -1.76,-2.435 -1.771,-2.419 -1.775,-2.4
  Top Layer region: 1.425,-2.4 1.425,-1.675 1.429,-1.656 1.44,-1.64 1.456,-1.629 1.475,-1.625 1.475,-1.625 1.725,-1.625 1.744,-1.629 1.76,-1.64 1.771,-1.656 1.775,-1.675 1.775,-1.675 1.775,-2.4 1.771,-2.419 1.76,-2.435 1.744,-2.446 1.725,-2.45 1.725,-2.45 1.475,-2.45 1.456,-2.446 1.44,-2.435 1.429,-2.419 1.425,-2.4
  Top Layer region: 1.425,1.675 1.425,2.4 1.429,2.419 1.44,2.435 1.456,2.446 1.475,2.45 1.475,2.45 1.725,2.45 1.744,2.446 1.76,2.435 1.771,2.419 1.775,2.4 1.775,2.4 1.775,1.675 1.771,1.656 1.76,1.64 1.744,1.629 1.725,1.625 1.725,1.625 1.475,1.625 1.456,1.629 1.44,1.64 1.429,1.656 1.425,1.675
  Top Layer region: -1.775,1.675 -1.775,2.4 -1.771,2.419 -1.76,2.435 -1.744,2.446 -1.725,2.45 -1.725,2.45 -1.475,2.45 -1.456,2.446 -1.44,2.435 -1.429,2.419 -1.425,2.4 -1.425,2.4 -1.425,1.675 -1.429,1.656 -1.44,1.64 -1.456,1.629 -1.475,1.625 -1.475,1.625 -1.725,1.625 -1.744,1.629 -1.76,1.64 -1.771,1.656 -1.775,1.675
  silkscreen extent -2.45,-2.7 2.45,2.7, body extent -2,-2.25 2,2.25, height 0.9
RNP0030A [mm] "QFN, 30-Leads, Body 6x4mm, Pitch 0.5mm, Thermal Pad 4.6x2.2mm"
  rrect40% 0.75x0.25 smd: 1(-1.825,2.5) 2(-1.825,2) 3(-1.825,1.5) 4(-1.825,1) 5(-1.825,0.5) 6(-1.825,0) 7(-1.825,-0.5) 8(-1.825,-1) 9(-1.825,-1.5) 10(-1.825,-2) 11(-1.825,-2.5) 16(1.825,-2.5) 17(1.825,-2) 18(1.825,-1.5) 19(1.825,-1) 20(1.825,-0.5) 21(1.825,0) 22(1.825,0.5) 23(1.825,1) 24(1.825,1.5) 25(1.825,2) 26(1.825,2.5)
  rrect40% 0.25x0.6 smd: 12(-0.75,-2.9) 13(-0.25,-2.9) 14(0.25,-2.9) 15(0.75,-2.9) 27(0.75,2.9) 28(0.25,2.9) 29(-0.25,2.9) 30(-0.75,2.9)
  rrect5% 2.2x4.6 smd paste-3: 31(0,0)
  rrect10% 0.98x0.96 on Top Paste: 31A(-0.59,1.74) 31A(-0.59,0.58) 31A(-0.59,-0.58) 31A(-0.59,-1.74) 31A(0.59,1.74) 31A(0.59,0.58) 31A(0.59,-0.58) 31A(0.59,-1.74)
  silkscreen extent -2.17,-3.18 2.17,3.18, body extent -2.07,-3.07 2.07,3.07, height 0.81
RUM0016A [mm] "QFN, 16-Leads, Body 4.1x4.1mm, Pitch 0.65mm, Thermal Pad 2.6x2.6mm"
  rect 0.6x0.3 smd: 1(-1.9,0.975) 2(-1.9,0.325) 3(-1.9,-0.325) 4(-1.9,-0.975) 9(1.9,-0.975) 10(1.9,-0.325) 11(1.9,0.325) 12(1.9,0.975)
  rect 0.3x0.6 smd: 5(-0.975,-1.9) 6(-0.325,-1.9) 7(0.325,-1.9) 8(0.975,-1.9) 13(0.975,1.9) 14(0.325,1.9) 15(-0.325,1.9) 16(-0.975,1.9)
  rect 2.6x2.6 smd paste-1.3: 17(0,0)
  silkscreen extent -2.17,-2.17 2.17,2.17, body extent -2.07,-2.07 2.07,2.07, height 0.8
SMB-Bi [mil] "Molded Diode, 2-Leads, Body 5.4x3.6mm, IPC Medium Density, based on OnSemi component dimensions"
  rect 85x107.99 smd: 1(-87.01,0) 2(87.01,0)
  silkscreen extent -125,-79 125,79, body extent -104,-73 104,73, height 89
XAL5030 [mil] "Coilcraft XAL5030 12/12/11"
  rect 46x183 smd: 1(-65,0) 2(65,0)
  silkscreen extent -108,-112 108,112, body extent -108,-112 108,112, height 122
XAL7030 [mm] "Coilcraft XAL7030 7.5 x.7.5 x 3.1 mm"
  rect 1.78x6.55 smd: 1(-2.36,0) 2(2.36,0)
  silkscreen extent -4,-4 4,4, body extent -4,-4 4,4, height 3.1

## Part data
0.9V 1.2V 1.8V 5V GND1 GND2 GND3 GND4: library part 1503-2, "Terminal, Turret, TH, Double", Manufacturer=Keystone, Supplier Part Number 1=1503-2K-ND
C0_2 C1_2 C2_2 C3_2: "CAP, CERM, 0.1 µF, 16 V, +/- 10%, X7R, 0603", Alternate Manufacturer=muRata, Alternate PartNumber=GRM155R71E104ME14D, Cap_Case=0603, Manufacturer=MuRata, Supplier Part Number 1=490-1532-1-ND, TempCo=X7R, Tolerance_%=10, Value1=Unknown, Value2=16V, ValueDisplayed=0.1µF
C0_3 C1_3 C2_3 C3_3: "CAP, CERM, 3300 pF, 50 V, +/- 10%, X7R, 0402", Cap_Case=0402, Manufacturer=MuRata, Supplier Part Number 1=490-3248-1-ND, TempCo=X7R, Tolerance_%=10, Value1=Unknown, Value2=50V, ValueDisplayed=3300pF
C1 C2 C3 C8 Cbias1: "CAP, CERM, 0.1 µF, 16 V, +/- 10%, X7R, AEC-Q200 Grade 1, 0603", Cap_Case=0603, Manufacturer=MuRata, Supplier Part Number 1=490-8015-1-ND, TempCo=X7R, Tolerance_%=10, Value1=Unknown, Value2=16V, ValueDisplayed=0.1µF
C4 C5 C6 C7: "CAP, CERM, 10 µF, 10 V, +/- 10%, X7R, 0805", Cap_Case=0805, Manufacturer=MuRata, Supplier Part Number 1=81-GCM21BR71A106KE2L, TempCo=X7R, Tolerance_%=10, Value1=Unknown, Value2=10V, ValueDisplayed=10µF
C9 C10: "CAP, CERM, 4700 pF, 100 V, +/- 5%, C0G/NP0, 0603", Cap_Case=0603, Manufacturer=Kemet, Supplier Part Number 1=399-9974-1-ND, TempCo=C0G/NP0, Tolerance_%=5, Value1=Unknown, Value2=100V, ValueDisplayed=4700pF
C11: "CAP, CERM, 2.2 µF, 50 V, +/- 10%, X5R, 0805", Cap_Case=0805, Manufacturer=TDK, Supplier Part Number 1=445-5976-1-ND, TempCo=X5R, Tolerance_%=10, Value1=Unknown, Value2=50V, ValueDisplayed=2.2µF
C16 C17 C24 C25: "CAP, CERM, 390 pF, 50 V, +/- 10%, X7R, 0402", Cap_Case=0402, Manufacturer=MuRata, Supplier Part Number 1=490-3249-1-ND, TempCo=X7R, Tolerance_%=10, Value1=Unknown, Value2=50V, ValueDisplayed=390pF
C18 C21 C26 C29: "CAP, CERM, 6800 pF, 50 V, +/- 10%, X7R, 0402", Cap_Case=0402, Manufacturer=MuRata, Supplier Part Number 1=490-4515-1-ND, TempCo=X7R, Tolerance_%=10, Value1=Unknown, Value2=50V, ValueDisplayed=6800pF
C19 C22 C27 C30: "CAP, CERM, 10 µF, 6.3 V, +/- 10%, X5R, 0805", Cap_Case=0805, Manufacturer=MuRata, Supplier Part Number 1=81-GRM21R60J106KE19L, TempCo=X5R, Tolerance_%=10, Value1="0.003 ohm", Value2=6.3V, ValueDisplayed=10µF
C20 C23 C28 C31 C34 C35 C38 C39 C44 C49 C51: "CAP, CERM, 0.1 µF, 16 V, +/- 5%, X7R, 0402", Cap_Case=0402, Manufacturer=MuRata, Supplier Part Number 1=490-6327-1-ND, TempCo=X7R, Tolerance_%=5, Value1=Unknown, Value2=16V, ValueDisplayed=0.1µF
C32 C33 C36 C37 C40 C41 C42 C43 C48 C50: "CAP, CERM, 10 µF, 10 V, +/- 10%, X7R, AEC-Q200 Grade 1, 1206", Cap_Case=1206, Manufacturer=MuRata, Supplier Part Number 1=490-4792-1-ND, TempCo=X7R, Tolerance_%=10, Value1=Unknown, Value2=10V, ValueDisplayed=10µF
C45 C47: "CAP, CERM, 2.2 µF, 10 V, +/- 10%, X5R, 0603", Cap_Case=0603, Manufacturer=MuRata, Supplier Part Number 1=490-1545-1-ND, TempCo=X5R, Tolerance_%=10, Value1=Unknown, Value2=10V, ValueDisplayed=2.2µF
C46: "CAP, CERM, 1 µF, 10 V, +/- 10%, X5R, 0603", Cap_Case=0603, Manufacturer=Kemet, Supplier Part Number 1=399-3118-1-ND, TempCo=X5R, Tolerance_%=10, Value1=Unknown, Value2=10V, ValueDisplayed=1µF
C52 C58: "CAP, CERM, 2200pF, 50V, +/-10%, X7R, 0603", Cap_Case=0603, Manufacturer=Kemet, Supplier Part Number 1=399-1085-1-ND, TempCo=X7R, Tolerance_%=10, Value1=Unknown, Value2=50V, ValueDisplayed=2200pF
C53: "CAP, CERM, 0.47uF, 10V, +/-10%, X7R, 0603", Cap_Case=0603, Manufacturer=MuRata, Supplier Part Number 1=GRM188R71A474KA61D-ND, TempCo=X7R, Tolerance_%=10, Value1=Unknown, Value2=10V, ValueDisplayed=0.47µF
C54 C55 C56 C57: "CAP, CERM, 22 µF, 10 V, +/- 10%, X7R, AEC-Q200 Grade 1, 1206", Cap_Case=1206, Manufacturer=MuRata, TempCo=X7R, Tolerance_%=10, Value1=Unknown, Value2=10V, ValueDisplayed=22µF
CB: "CAP, CERM, 0.47uF, 25V, +/-10%, X5R, 0603", Cap_Case=0603, Manufacturer=MuRata, Supplier Part Number 1=GRM188R61E474KA12D-ND, TempCo=X5R, Tolerance_%=10, Value1=Unknown, Value2=25V, ValueDisplayed=0.47µF
Cbulk1: "CAP, Aluminum Polymer, 100 µF, 50 V, +/- 20%, 0.025 ohm, AEC-Q200 Grade 2, D10xL10mm SMD", Cap_Case=10x10mm, Manufacturer=Chemi-Con, Supplier Part Number 1=565-4187-1-ND, Tolerance_%=20, Value1="0.025 ohm", Value2=50V, ValueDisplayed=100µF
CF1 CF2: "CAP, CERM, 4.7 µF, 50 V, +/- 20%, X7R, AEC-Q200 Grade 1, 1210", Cap_Case=1210, Manufacturer=TDK, Supplier Part Number 1=445-13030-1-ND, TempCo=X7R, Tolerance_%=20, Value1=Unknown, Value2=50V, ValueDisplayed=4.7µF
CFF: "CAP, CERM, 4.7 pF, 50 V, +/- 5%, C0G/NP0, 0603", Cap_Case=0603, Manufacturer=AVX, Supplier Part Number 1=478-1159-1-ND, TempCo=C0G/NP0, Tolerance_%=5, Value1="0.633 ohm", Value2=50V, ValueDisplayed=4.7pF
CI1 CO: "CAP, CERM, 0.47 µF, 50 V, +/- 10%, X7R, 0805", Cap_Case=0805, Manufacturer=MuRata, Supplier Part Number 1=490-3328-1-ND, TempCo=X7R, Tolerance_%=10, Value1=Unknown, Value2=50V, ValueDisplayed=0.47µF
CI2 CI3: "CAP, CERM, 10 µF, 50 V, +/- 10%, X7R, 1210", Cap_Case=1210, Manufacturer=MuRata, Supplier Part Number 1=490-6544-1-ND, TempCo=X7R, Tolerance_%=10, Value1=Unknown, Value2=50V, ValueDisplayed=10µF
CO1 CO2 CO3 CO4 CO5: "CAP, CERM, 22 µF, 16 V, +/- 10%, X7R, 1210", Cap_Case=1210, Manufacturer=MuRata, Supplier Part Number 1=490-4524-1-ND, TempCo=X7R, Tolerance_%=10, Value1="0.003 ohm", Value2=16V, ValueDisplayed=22µF
CSS: "CAP, CERM, 0.01 µF, 100 V, +/- 20%, X7R, 0603", Cap_Case=0603, Manufacturer=AVX, Supplier Part Number 1=478-3701-1-ND, TempCo=X7R, Tolerance_%=20, Value1="0.098 ohm", Value2=100V, ValueDisplayed=0.01µF
CVCC: "CAP, CERM, 2.2uF, 10V, +/-10%, X6S, 0603", Cap_Case=0603, Manufacturer=MuRata, Supplier Part Number 1=490-4521-1-ND, TempCo=X6S, Tolerance_%=10, Value1=Unknown, Value2=10V, ValueDisplayed=2.2µF
D1: "Diode, TVS, Bi, 28 V, 45.4 Vc, SMB", Manufacturer="Diodes Inc.", Power_W=5, Supplier Part Number 1=SMBJ28CA-FDICT-ND, Value1=5W
FB1: "Ferrite Bead, 800 ohm @ 100 MHz, 8 A, 2220", Manufacturer="Laird-Signal Integrity Products", Supplier Part Number 1=240-2433-1-ND, Value1="0.01 ohm", Value2=8A, ValueDisplayed="800 ohm"
FID1 FID2 FID3 FID4 FID5 FID6: "Fiducial mark.  There is nothing to buy or mount.", Manufacturer=N/A
GND_: library part 6092, "Standard Banana Jack, Insulated, Black", Manufacturer=Keystone, Supplier Part Number 1=6092K-ND
IN: library part 6091, "Standard Banana Jack, Insulated, Red", Manufacturer=Keystone, Supplier Part Number 1=6091K-ND
L1: "Inductor, Shielded, Composite, 2.2 µH, 12.9 A, 0.0137 ohm, SMD", Manufacturer=Coilcraft, Value1="0.0137 ohm", Value2=12.9A, ValueDisplayed=2.2µH
L2 L3 L4 L5: "Ferrite Bead, 30 ohm @ 100 MHz, 4 A, 0805", Manufacturer=MuRata, Supplier Part Number 1=490-11049-1-ND, Value1="0.014 ohm", Value2=4A
L6 L7 L8 L9: "Inductor, Powdered Iron, 470 nH, 5.8 A, 0.017 ohm, SMD", Manufacturer="MuRata Toko", PartNumber=DFE252012F-R47M{}P2, Value1="0.017 ohm", Value2=5.8A, ValueDisplayed=470nH
L10 L11: "Inductor, Shielded, Composite, 1.2 µH, 11.1 A, 0.01 ohm, SMD", Manufacturer=Coilcraft, Value1="0.01 ohm", Value2=11.1A, ValueDisplayed=1.2µH
LF1: "Inductor, Shielded, Composite, 2.2 µH, 9.2 A, 0.01 ohm, SMD", Manufacturer=Coilcraft, Value1="0.01 ohm", Value2=9.2A, ValueDisplayed=2.2µH
Logo2: library part Pb-Free
Logo3: library part FCC_disclaimer, "FCC_disclaimer"
LOGO4: library part IEC_HotSurface, "IEC 61010-1 Hot Surface Warning"
NTGND: "Single point connection between nets."
Q1: "MOSFET, N-CH, 40 V, 75 A, PowerPAK_SO-8L", Alternate Manufacturer=None, Manufacturer=Vishay-Siliconix, Supplier Part Number 1=SQJ422EP-T1-GE3-ND, Value1="0.0043 ohm", Value2="67 nC"
R1 R2 R3 R4: "RES, 3.9, 5%, 0.125 W, 0805", Manufacturer=Vishay-Dale, Power_W=0.125, Supplier Part Number 1=541-3.9ACT-ND, TempCo="200 ppm/C", Tolerance_%=5, Value1=5%, Value2=0.125W, Value_Code=3R90, ValueDisplayed=3.9
R5 R6 R7 R8: "RES, 100 k, 1%, 0.063 W, 0402", Manufacturer=Vishay-Dale, Power_W=0.063, Supplier Part Number 1=541-100KLCT-ND, TempCo="100 ppm/C", Tolerance_%=1, Value1=1%, Value2=0.063W, Value_Code=100k
R9: "RES, 4.99 ohm, 1%, 0.125W, 0805", Manufacturer="Yageo America", Power_W=0.125, Supplier Part Number 1=311-4.99CRCT-ND, TempCo="200 ppm/C", Tolerance_%=1, Value1=1%, Value2=0.125W, Value_Code=4R99
R10 R16: "RES, 4.7 ohm, 5%, 0.125W, 0805", Manufacturer=Vishay-Dale, Power_W=0.125, Supplier Part Number 1=541-4.7ACT-ND, TempCo="200 ppm/C", Tolerance_%=5, Value1=5%, Value2=0.125W, Value_Code=4R70
R11 R13: "RES, 49.9k ohm, 1%, 0.1W, 0603", Manufacturer=Vishay-Dale, Power_W=0.1, Supplier Part Number 1=541-49.9KHCT-ND, TempCo="100 ppm/C", Tolerance_%=1, Value1=1%, Value2=0.1W, Value_Code=49k9
R12: "RES, 12.4k ohm, 1%, 0.1W, 0603", Manufacturer=Vishay-Dale, Power_W=0.1, Supplier Part Number 1=541-12.4KHCT-ND, TempCo="100 ppm/C", Tolerance_%=1, Value1=1%, Value2=0.1W, Value_Code=12k4
R14: "RES, 4.99 k, 1%, 0.1 W, 0603", Manufacturer=Vishay-Dale, Power_W=0.1, Supplier Part Number 1=541-4.99KHCT-ND, TempCo="100 ppm/C", Tolerance_%=1, Value1=1%, Value2=0.1W, Value_Code=4k99, ValueDisplayed=4.99k
R15 R17: "RES, 10k ohm, 5%, 0.1W, 0603", Manufacturer=Vishay-Dale, Power_W=0.1, Supplier Part Number 1=541-10KGCT-ND, TempCo="200 ppm/C", Tolerance_%=5, Value1=5%, Value2=0.1W, Value_Code=10k0
Rbias1: "RES, 3.0, 5%, 0.063 W, 0402", Manufacturer=Vishay-Dale, Power_W=0.063, Supplier Part Number 1=541-3.0JCT-ND, TempCo="200 ppm/C", Tolerance_%=5, Value1=5%, Value2=0.063W, Value_Code=3R00, ValueDisplayed=3.0
RFBB: "RES, 432 k, 1%, 0.1 W, 0603", Manufacturer=Vishay-Dale, Power_W=0.1, Supplier Part Number 1=541-432KHCT-ND, TempCo="100 ppm/C", Tolerance_%=1, Value1=1%, Value2=0.1W, Value_Code=432k
RFBT: "RES, 1.00 M, 1%, 0.1 W, 0603", Manufacturer=Vishay-Dale, Power_W=0.1, Supplier Part Number 1=541-1.00MHCT-ND, TempCo="100 ppm/C", Tolerance_%=1, Value1=1%, Value2=0.1W, Value_Code=1M00, ValueDisplayed=1.00M
RPG: "RES, 100 k, 1%, 0.1 W, 0603", Manufacturer=Vishay-Dale, Power_W=0.1, Supplier Part Number 1=541-100KHCT-ND, TempCo="100 ppm/C", Tolerance_%=1, Value1=1%, Value2=0.1W, Value_Code=100k
RT: "RES, 17.4 k, 1%, 0.1 W, 0603", Manufacturer=Vishay-Dale, Power_W=0.1, Supplier Part Number 1=541-17.4KHCT-ND, TempCo="100 ppm/C", Tolerance_%=1, Value1=1%, Value2=0.1W, Value_Code=17k4, ValueDisplayed=17.4k
U1: library part LM74700QDDCRQ1, "Low Iq Always ON Smart Diode Controller, DDC0006A (SOT-6)", Alternate Manufacturer="Texas Instruments"
U2: "3.5V to 36V 5A Synchronous Step-Down Voltage Regulator, RNP0030A (WQFN-30)", Alternate Manufacturer="Texas Instruments", Alternate PartNumber=LM73605QRNPTQ1
U3: library part LP8756-Q1RNF, "Four-Phase Buck Converter, RNF0026C (VQFN-HR-26)", Alternate Manufacturer="Texas Instruments"
U4: "Switched Capacitor 5 V Boost Converter, DSG0008A (WSON-8)", Alternate Manufacturer="Texas Instruments", Alternate PartNumber=LM2775DSGT
U5: "Dual 2-A, High Frequency Synchronous Buck Regulator, RUM0016A (WQFN-16)", Alternate Manufacturer="Texas Instruments"

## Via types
v1: diameter 20, hole 10, Top Layer to Bottom Layer, 270 vias
v2: diameter 16, hole 8, Top Layer to Bottom Layer, 134 vias
v3: diameter 19.68, hole 7.87, Top Layer to Bottom Layer, 21 vias
v4: diameter 16/16/16/16 (per signal layer), hole 8, Top Layer to Bottom Layer, 1 vias

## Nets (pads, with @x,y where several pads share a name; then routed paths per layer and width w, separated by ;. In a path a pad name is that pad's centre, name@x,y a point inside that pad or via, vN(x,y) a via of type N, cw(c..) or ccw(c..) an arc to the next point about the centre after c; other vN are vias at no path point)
0.9V: 0.9V.1 C0_2.2 C0_3.1 C1_2.2 C1_3.1 C2_2.2 C2_3.1 C3_2.2 C3_3.1 C32.1 C33.1 C36.1 C37.1 C40.1 C41.1 C42.1 C43.1 L6.2 L7.2 L8.2 L9.2 U3.8 | length 398.3
  Top Layer w8: U3.8@3738.15,1096.85 U3.8@3729.8,1096.85 3747.95,1115 v2(3750,1115)
  Signal Layer 2 w8: v2(3750,1115) 3854,1115 3910,1171 v1(3910,1350)
  other v1: 3040,555 3090,555 3140,555 3190,555 3250,555 3300,555 3355,555 3935,565 3985,565 4035,565 4085,565 4145,565 4195,565 4250,565 3040,690 3090,690 3140,690 3195,690 3250,690 3300,690 3355,690 3935,700 3985,700 4035,700 4090,700 4145,700 4195,700 4250,700 3045,1350 3095,1350 3145,1350 3195,1350 3255,1350 3305,1350 3360,1350 3960,1350 4010,1350 4060,1350 4120,1350 4170,1350 4225,1350 3045,1485 3095,1485 3145,1485 3200,1485 3255,1485 3305,1485 3360,1485 3910,1485 3960,1485 4010,1485 4065,1485 4120,1485 4170,1485 4225,1485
